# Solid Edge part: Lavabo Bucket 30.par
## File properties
Title: LAVABO BUCKET 30
Author: DESYS
Template: Iso Part.par
Last saved by: PIM_1
Revision: 41
Application: Solid Edge
Tipo di contenuto documento: 0
Accuracy: 0,990
Document Number: 8801
Revision: 0
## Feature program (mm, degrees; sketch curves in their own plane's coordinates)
lofted protrusion "unnamed LoftedProtrusion 1"
sketch for "ScavoEstrusione_2" plane through (0, 0, 235) normal (0, 0, 1) x-axis (1, 0, 0)
  circle centre (0, 0) radius 120
extrude "ScavoEstrusione_2" cut finite 86 along -normal  Treatment1_DraftAngle = 13.5 deg
sketch for "ScavoEstrusione_3" plane through (0, 0, 0) normal (0, 0, -1) x-axis (0, 1, 0)
  circle centre (0, 0) radius 77.5
extrude "ScavoEstrusione_3" cut finite 120 along -normal
sketch for "ScavoEstrusione_5" plane through (0, 0, 149) normal (0, 0, 1) x-axis (1, 0, 0)
  circle centre (0, 0) radius 22.5
extrude "ScavoEstrusione_5" cut finite 455 along -normal
fillet "Rotondo_1" radius 10
sketch for "ProtrusioneEstrusa_1" #1 plane through (0, 0, 120) normal (0, 0, -1) x-axis (-1, 0, 0)
  circle centre (0, 0) radius 32.5
sketch for "ProtrusioneEstrusa_1" #2 plane through (0, 0, 120) normal (0, 0, -1) x-axis (-1, 0, 0)
  circle centre (0, 0) radius 22.5
extrude "ProtrusioneEstrusa_1" add finite 35 along +normal
sketch for "ScavoEstrusione_8" plane through (0, -132.5, 117.5) normal (0, -0.98909, -0.147311) x-axis (0, -0.147311, 0.98909)
  circle centre (73.796, 0) radius 10
extrude "ScavoEstrusione_8" cut finite 5 along -normal
fillet "Rotondo_2" radius 20
fillet "Rotondo_3" radius 10
fillet "Rotondo_4" radius 5
fillet "Rotondo_6" radius 5
fillet "Rotondo_7" radius 2
sketch for "ScavoEstrusione_9" #1 plane through (0, 0, 0) normal (0, 0, -1) x-axis (1, 0, 0)
sketch for "ScavoEstrusione_9" #2 plane through (0, 0, 0) normal (0, 0, -1) x-axis (1, 0, 0)
extrude "ScavoEstrusione_9" cut finite 20 along -normal
fillet "Rotondo_8" radius 2
sketch for "ScavoEstrusione_14" plane through (0, -150, 0) normal (0, -1, 0) x-axis (1, 0, 0)
extrude "ScavoEstrusione_14" cut finite 25 along -normal
fillet "Rotondo_5" radius 2
mirror "unnamed Mirror 1" of "ScavoEstrusione_8", "ScavoEstrusione_14", "Rotondo_5" about plane through (18.6777, 0, 18.6777) normal (0, 1, 0)
extrude "unnamed Cutout 1" cut finite 5
extrude "unnamed Cutout 2" cut finite 25
fillet "unnamed Round 1"
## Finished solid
Body 1: solid body, 32 faces, 32 edges, 0 vertices.
  Faces by surface: torus 12, plane 9, cylinder 7, blend 2, cone 2
  Edges by curve: circle 28, intersection 4
Bounding box of the edges (mm; curved faces can reach further): 298.291 x 298.291 x 235.000, from (-149.1456, -149.1456, 0) to (149.1456, 149.1456, 235).
Cylindrical faces by radius (mm): R7.5 x2, R10 x2, R22.5 x1, R32.5 x1, R77.5 x1
Conical faces (half-angle, radius in mm at the cone's reference point): 8.4711 deg R150 x1, 13.5 deg R120 x1
Toroidal faces (ring radius, tube radius in mm): R9.5 r2 x2, R24.5 r2 x1, R30.5 r2 x1, R32.5 r10 x1, R37.5 r5 x1, R67.5 r10 x1, R82.5 r5 x1, R83.5865 r20 x1, R110.6895 r5 x1, R123.9417 r5 x1, R144.2002 r5 x1
Planar faces by outward normal: +y 1, +z 2, -y 1, -z 5
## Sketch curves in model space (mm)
line (50.0001, -142.8659, 190.4909) -> (0.0001, -142.8659, 190.4909)
line (-0.0001, 141.8979, 190.4909) -> (-15.0001, 141.8979, 190.4909)
line (50.0001, 141.8979, 190.4909) -> (-0.0001, 141.8979, 190.4909)
arc centre (50.0001, -0.484, 190.4909) radius 142.3819 from (50.0001, 141.8979, 190.4909) through (192.3195, -4.7033, 190.4909) to (50.0001, -142.8659, 190.4909)
line (-115, 0, 0) -> (-150, 0, 235)
line (150, 0, 235) -> (115, 0, 0)
circle centre (0, 0, 235) radius 150
circle centre (0, 0, 0) radius 115
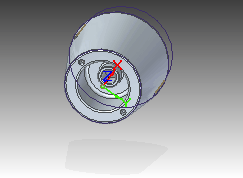
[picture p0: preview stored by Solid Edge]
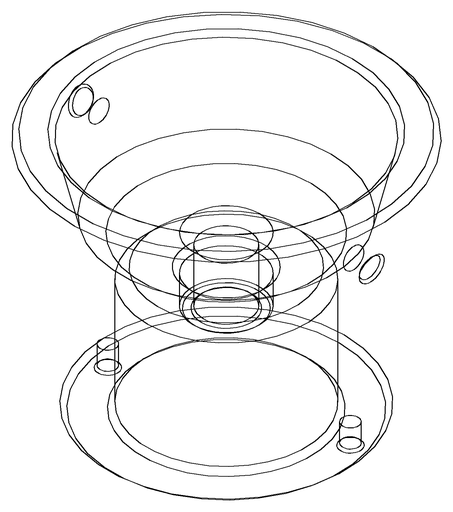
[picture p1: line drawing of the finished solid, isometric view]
